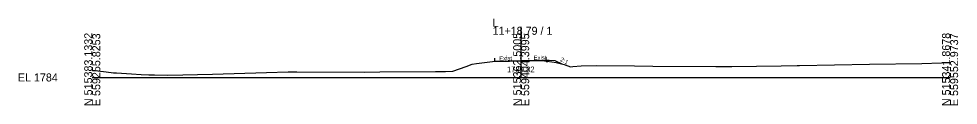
# Model space of a CAD drawing. Extents: x -26 to 1303, y -10 to 9545.
# Drawn here: x -25.7 to 302.8, y 2490.3 to 2520.5 of the extents above; entities that cross this region are included whole.
import ezdxf

# ---------------------------------------------------------------- set-up
doc = ezdxf.new("R2010")
doc.units = 0
for name, color, linetype in [('Exist Cross Section Cell', 7, 'Continuous'), ('Exist XS Center Line Elevation Label', 7, 'Continuous'), ('Exist XS Ground Line', 7, 'Continuous'), ('Prop XS Ditch Slope Text', 7, 'Continuous'), ('Prop XS EOT Tick Mark', 7, 'Continuous'), ('Prop XS Finish Grade', 7, 'Continuous'), ('Prop XS Finish Grade Earthwork', 7, 'Continuous'), ('Prop XS Finish Grade Pavement', 7, 'Continuous'), ('Prop XS Pvmt Edge Slope', 7, 'Continuous'), ('Prop XS SE Text', 7, 'Continuous'), ('Prop XS Subgrade Earthwork', 7, 'Continuous')]:
    doc.layers.add(name, color=color, linetype=linetype)

msp = doc.modelspace()

# ---------------------------------------------------------------- linework, layer by layer
at = {"layer": 'Exist Cross Section Cell'}
for p, q in [((150, 2500), (150, 2517.71)), ((0, 2500), (150, 2500)), ((150, 2500), (300, 2500))]:
    msp.add_line(p, q, dxfattribs=at)
at = {"layer": 'Exist XS Ground Line'}
for p, q in [((126.14, 2502.21), (130.73, 2503.87)), ((130.73, 2503.87), (132.9, 2504.62)), ((132.9, 2504.62), (134.42, 2504.83)), ((134.42, 2504.83), (139.99, 2505.54)), ((139.99, 2505.54), (145.96, 2505.71)), ((145.96, 2505.71), (149.18, 2505.81)), ((149.18, 2505.81), (150, 2505.82)), ((150, 2505.82), (152.98, 2505.86)), ((152.98, 2505.86), (157.21, 2505.9)), ((157.21, 2505.9), (160.75, 2505.48)), ((160.75, 2505.48), (162.18, 2505.29)), ((162.18, 2505.29), (165.01, 2504.48)), ((165.01, 2504.48), (167.21, 2503.77)), ((167.21, 2503.77), (168.06, 2503.78)), ((168.06, 2503.78), (170.98, 2504.02)), ((170.98, 2504.02), (176.44, 2504.13)), ((176.44, 2504.13), (189.69, 2504.03)), ((189.69, 2504.03), (196.04, 2503.94)), ((196.04, 2503.94), (218.12, 2503.82)), ((218.12, 2503.82), (221.27, 2503.82)), ((221.27, 2503.82), (223.66, 2503.81)), ((223.66, 2503.81), (240.88, 2504.07)), ((240.88, 2504.07), (246.49, 2504.15)), ((246.49, 2504.15), (247.39, 2504.17)), ((247.39, 2504.17), (271.76, 2504.61)), ((271.76, 2504.61), (290.15, 2504.88)), ((290.15, 2504.88), (296.99, 2505.1)), ((296.99, 2505.1), (300, 2505.22)), ((0, 2502.58), (4.81, 2501.95)), ((4.81, 2501.95), (7.47, 2501.63)), ((7.47, 2501.63), (8.44, 2501.6)), ((8.44, 2501.6), (13.68, 2501.27)), ((13.68, 2501.27), (17.1, 2501.07)), ((17.1, 2501.07), (19.74, 2500.97)), ((19.74, 2500.97), (21.74, 2500.93)), ((21.74, 2500.93), (26.44, 2500.84)), ((26.44, 2500.84), (42.07, 2501.21)), ((42.07, 2501.21), (60.92, 2501.74)), ((60.92, 2501.74), (68.55, 2501.93)), ((68.55, 2501.93), (69.85, 2501.94)), ((69.85, 2501.94), (71.56, 2501.96)), ((71.56, 2501.96), (95.07, 2501.9)), ((95.07, 2501.9), (100.61, 2501.98)), ((100.61, 2501.98), (120.01, 2502.07)), ((120.01, 2502.07), (123.57, 2502.08)), ((123.57, 2502.08), (126.14, 2502.21))]:
    msp.add_line(p, q, dxfattribs=at)
at = {"layer": 'Prop XS EOT Tick Mark'}
for p, q in [((140.79, 2505.73), (140.79, 2506.73)), ((158.77, 2506.09), (158.77, 2507.09))]:
    msp.add_line(p, q, dxfattribs=at)
at = {"layer": 'Prop XS Finish Grade'}
msp.add_line((158.77, 2506.09), (159.79, 2506.05), dxfattribs=at)
at = {"layer": 'Prop XS Finish Grade Earthwork'}
for p, q in [((159.79, 2506.05), (161.77, 2505.93)), ((161.77, 2505.93), (164.2, 2504.71))]:
    msp.add_line(p, q, dxfattribs=at)
at = {"layer": 'Prop XS Finish Grade Pavement'}
for p, q in [((140.79, 2505.73), (150, 2505.95)), ((150, 2505.95), (158.77, 2506.09))]:
    msp.add_line(p, q, dxfattribs=at)
at = {"layer": 'Prop XS Pvmt Edge Slope'}
msp.add_line((158.77, 2506.09), (159.3, 2505.56), dxfattribs=at)
at = {"layer": 'Prop XS Subgrade Earthwork'}
for p, q in [((158.77, 2505.55), (158.77, 2505.72)), ((158.77, 2505.55), (159.3, 2505.56)), ((159.3, 2505.56), (159.79, 2506.05))]:
    msp.add_line(p, q, dxfattribs=at)

# ---------------------------------------------------------------- texts
at = {"layer": 'Exist Cross Section Cell'}
for s, p in [('L', (140, 2517.71)), ('11+18.79 / 1', (140, 2514.91)), ('EL 1784', (-26, 2498.6))]:
    msp.add_text(s, height=2.8, dxfattribs=at).set_placement(p)
for s, p in [('N 515383.1332', (0, 2490)), ('E 559255.8253', (2.8, 2490)), ('N 515362.5005', (150, 2490)), ('E 559404.3995', (152.8, 2490)), ('N 515341.8678', (300, 2490)), ('E 559552.9737', (302.8, 2490))]:
    msp.add_text(s, height=2.8, rotation=90, dxfattribs=at).set_placement(p)
at = {"layer": 'Exist XS Center Line Elevation Label'}
msp.add_text('1789.82', height=2, dxfattribs=at).set_placement((145.02, 2501.82))
at = {"layer": 'Prop XS Ditch Slope Text'}
msp.add_text('2:1', height=1.5, rotation=333.4349, dxfattribs=at).set_placement((163.47, 2505.81))
at = {"layer": 'Prop XS SE Text'}
for p in [(142.33, 2505.93), (154.36, 2506.12)]:
    msp.add_text('Exist', height=1.5, rotation=1.3214, dxfattribs=at).set_placement(p)

doc.saveas('drawing.dxf')
